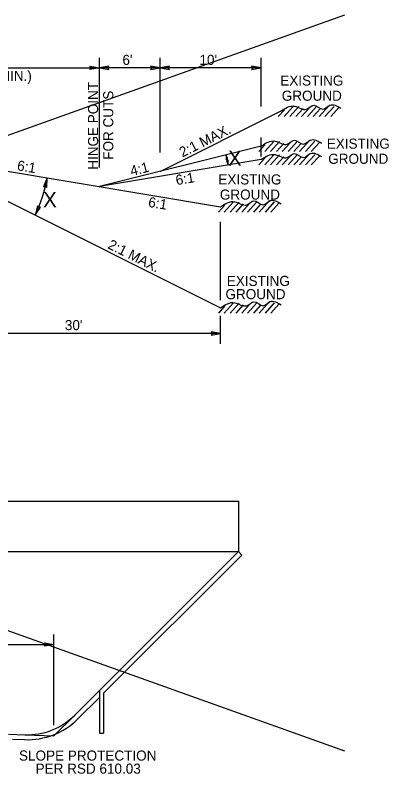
# Model space of a CAD drawing. Extents: x 1553195 to 1553792, y 810516 to 810787.
# Drawn here: x 1553619.9 to 1553656.8, y 810531.5 to 810606.6 of the extents above; entities that cross this region are included whole.
import ezdxf

# ---------------------------------------------------------------- set-up
doc = ezdxf.new("R2010")
doc.units = 0
for name, color, linetype in [('Prop DSN Text', 7, 'Continuous'), ('Prop Pavement Schedule Description CELL', 7, 'Continuous'), ('Sheet Sticker Incomplete CELL', 7, 'Continuous'), ('Typical Arrow Superelevation CELL', 7, 'Continuous'), ('Typical Text General CELL', 7, 'Continuous'), ('z - Construction', 7, 'Continuous')]:
    doc.layers.add(name, color=color, linetype=linetype)

msp = doc.modelspace()

# ---------------------------------------------------------------- linework, layer by layer
at = {"layer": 'Prop DSN Text'}
for points in [[(1553627.268, 810601.535), (1553628.206, 810601.374), (1553627.263, 810601.207), (1553627.383, 810601.374)], [(1553629.143, 810601.535), (1553628.206, 810601.374), (1553629.148, 810601.207), (1553629.028, 810601.374)], [(1553633.268, 810601.212), (1553634.206, 810601.374), (1553633.263, 810601.54), (1553633.383, 810601.374)], [(1553635.143, 810601.535), (1553634.206, 810601.374), (1553635.148, 810601.207), (1553635.028, 810601.374)], [(1553643.268, 810601.212), (1553644.206, 810601.374), (1553643.263, 810601.54), (1553643.383, 810601.374)], [(1553640.923, 810592.322), (1553640.736, 810592.76), (1553640.764, 810592.282), (1553640.831, 810592.36)], [(1553640.782, 810592.197), (1553640.946, 810591.751), (1553640.943, 810592.229), (1553640.872, 810592.155)], [(1553623.017, 810589.537), (1553623.043, 810590.488), (1553622.694, 810589.596), (1553622.881, 810589.681)], [(1553622.092, 810587.726), (1553621.846, 810586.807), (1553622.392, 810587.593), (1553622.191, 810587.554)], [(1553639.268, 810574.9), (1553640.206, 810575.062), (1553639.263, 810575.228), (1553639.383, 810575.062)], [(1553622.768, 810544.426), (1553623.706, 810544.264), (1553622.763, 810544.098), (1553622.883, 810544.264)]]:
    msp.add_lwpolyline(points, close=True, dxfattribs=at)
at = {"layer": 'Prop Pavement Schedule Description CELL'}
for p, q in [((1553628.206, 810591.507), (1553628.206, 810602.374)), ((1553640.206, 810578.372), (1553640.206, 810586.148)), ((1553640.206, 810574.062), (1553640.206, 810576.817)), ((1553623.706, 810536.295), (1553623.706, 810545.264))]:
    msp.add_line(p, q, dxfattribs=at)
for centre, radius, start, end in [((1553628.206, 810589.627), 12.916, 9.46232, 14.03624), ((1553610.206, 810592.627), 13.014, 333.43495, 350.53768)]:
    msp.add_arc(centre, radius, start, end, dxfattribs=at)
at = {"layer": 'Sheet Sticker Incomplete CELL'}
for p, q in [((1553634.206, 810591.127), (1553646.125, 810597.087)), ((1553644.206, 810593.627), (1553628.206, 810589.627)), ((1553610.206, 810592.627), (1553640.206, 810587.627)), ((1553610.206, 810592.627), (1553640.206, 810577.627)), ((1553644.206, 810592.294), (1553628.206, 810589.627))]:
    msp.add_line(p, q, dxfattribs=at)
at = {"layer": 'Typical Arrow Superelevation CELL'}
for p, q in [((1553652.472, 810606.601), (1553448.543, 810533.73)), ((1553448.543, 810606.601), (1553652.472, 810533.73)), ((1553446.448, 810558.478), (1553641.963, 810558.478)), ((1553641.963, 810558.478), (1553641.963, 810553.478)), ((1553446.448, 810553.478), (1553641.963, 810553.478)), ((1553625.739, 810537.254), (1553641.963, 810553.478)), ((1553641.963, 810553.478), (1553642.309, 810553.133)), ((1553628.628, 810539.452), (1553642.309, 810553.133)), ((1553628.206, 810539.687), (1553628.206, 810535.478)), ((1553626.084, 810536.908), (1553628.206, 810539.03)), ((1553628.628, 810539.452), (1553628.628, 810535.478)), ((1553623.706, 810535.22), (1553625.739, 810537.254)), ((1553619.206, 810535.398), (1553620.832, 810535.334)), ((1553620.832, 810535.334), (1553623.706, 810535.22)), ((1553628.206, 810535.478), (1553628.628, 810535.478)), ((1553619.628, 810534.893), (1553620.813, 810534.846))]:
    msp.add_line(p, q, dxfattribs=at)
for radius in [7.06, 6.572]:
    msp.add_arc((1553621.092, 810541.901), radius, 267.73793, 315, dxfattribs=at)
at = {"layer": 'Typical Text General CELL'}
for p, q in [((1553647.361, 810597.529), (1553646.486, 810596.556)), ((1553647.956, 810597.55), (1553647.062, 810596.556)), ((1553649.715, 810597.585), (1553648.79, 810596.556)), ((1553650.964, 810597.692), (1553649.942, 810596.556)), ((1553651.429, 810597.569), (1553650.518, 810596.556)), ((1553646.512, 810597.225), (1553645.91, 810596.556)), ((1553648.366, 810597.366), (1553647.638, 810596.556)), ((1553648.99, 810597.419), (1553648.214, 810596.556)), ((1553650.076, 810597.345), (1553649.366, 810596.556)), ((1553651.891, 810597.443), (1553651.094, 810596.556)), ((1553644.593, 810593.765), (1553643.991, 810593.097)), ((1553645.442, 810594.069), (1553644.567, 810593.097)), ((1553646.037, 810594.091), (1553645.143, 810593.097)), ((1553646.447, 810593.906), (1553645.719, 810593.097)), ((1553647.071, 810593.959), (1553646.295, 810593.097)), ((1553647.796, 810594.125), (1553646.871, 810593.097)), ((1553648.157, 810593.886), (1553647.447, 810593.097)), ((1553649.045, 810594.232), (1553648.023, 810593.097)), ((1553649.51, 810594.11), (1553648.599, 810593.097)), ((1553649.972, 810593.983), (1553649.175, 810593.097)), ((1553644.593, 810592.432), (1553643.991, 810591.764)), ((1553645.442, 810592.736), (1553644.567, 810591.764)), ((1553646.037, 810592.757), (1553645.143, 810591.764)), ((1553646.447, 810592.573), (1553645.719, 810591.764)), ((1553647.071, 810592.626), (1553646.295, 810591.764)), ((1553647.796, 810592.792), (1553646.871, 810591.764)), ((1553648.157, 810592.553), (1553647.447, 810591.764)), ((1553649.045, 810592.899), (1553648.023, 810591.764)), ((1553649.51, 810592.776), (1553648.599, 810591.764)), ((1553649.972, 810592.65), (1553649.175, 810591.764)), ((1553640.593, 810587.765), (1553639.991, 810587.097)), ((1553641.442, 810588.069), (1553640.567, 810587.097)), ((1553642.037, 810588.091), (1553641.143, 810587.097)), ((1553642.447, 810587.906), (1553641.719, 810587.097)), ((1553643.071, 810587.959), (1553642.295, 810587.097)), ((1553643.796, 810588.125), (1553642.871, 810587.097)), ((1553644.157, 810587.886), (1553643.447, 810587.097)), ((1553645.045, 810588.232), (1553644.023, 810587.097)), ((1553645.51, 810588.11), (1553644.599, 810587.097)), ((1553645.972, 810587.983), (1553645.175, 810587.097)), ((1553641.442, 810578.069), (1553640.567, 810577.097)), ((1553642.037, 810578.091), (1553641.143, 810577.097)), ((1553643.071, 810577.959), (1553642.295, 810577.097)), ((1553643.796, 810578.125), (1553642.871, 810577.097)), ((1553645.045, 810578.232), (1553644.023, 810577.097)), ((1553645.51, 810578.11), (1553644.599, 810577.097)), ((1553645.972, 810577.983), (1553645.175, 810577.097)), ((1553640.593, 810577.765), (1553639.991, 810577.097)), ((1553642.447, 810577.906), (1553641.719, 810577.097)), ((1553644.157, 810577.886), (1553643.447, 810577.097))]:
    msp.add_line(p, q, dxfattribs=at)
for points in [[(1553646.125, 810597.087), (1553647.519, 810597.585), (1553648.714, 810597.286), (1553649.411, 810597.685), (1553650.307, 810597.286), (1553651.004, 810597.685), (1553652.1, 810597.386)], [(1553644.206, 810593.627), (1553645.6, 810594.126), (1553646.795, 810593.827), (1553647.492, 810594.225), (1553648.388, 810593.827), (1553649.086, 810594.225), (1553650.181, 810593.926)], [(1553644.206, 810592.294), (1553645.6, 810592.792), (1553646.795, 810592.493), (1553647.492, 810592.892), (1553648.388, 810592.493), (1553649.086, 810592.892), (1553650.181, 810592.593)], [(1553640.206, 810587.627), (1553641.6, 810588.126), (1553642.795, 810587.827), (1553643.492, 810588.225), (1553644.388, 810587.827), (1553645.086, 810588.225), (1553646.181, 810587.926)], [(1553640.206, 810577.627), (1553641.6, 810578.126), (1553642.795, 810577.827), (1553643.492, 810578.225), (1553644.388, 810577.827), (1553645.086, 810578.225), (1553646.181, 810577.926)]]:
    msp.add_spline(points, degree=3, dxfattribs=at)
at = {"layer": 'z - Construction'}
for p, q in [((1553634.206, 810592.994), (1553634.206, 810602.374)), ((1553644.206, 810597.541), (1553644.206, 810602.374)), ((1553610.206, 810601.374), (1553628.206, 810601.374)), ((1553634.206, 810601.374), (1553628.206, 810601.374)), ((1553644.206, 810601.374), (1553634.206, 810601.374)), ((1553644.206, 810592.603), (1553644.206, 810594.493)), ((1553640.206, 810575.062), (1553610.206, 810575.062)), ((1553610.206, 810544.264), (1553623.706, 810544.264))]:
    msp.add_line(p, q, dxfattribs=at)

# ---------------------------------------------------------------- texts
at = {"layer": 'Prop Pavement Schedule Description CELL'}
for s, height, p in [("6'", 1, (1553630.491, 810601.674)), ("10'", 1, (1553638.11, 810601.674)), ("(15' MIN.)", 1, (1553615.698, 810600.086)), ('EXISTING', 1, (1553646.106, 810599.625)), ('GROUND', 1, (1553646.255, 810598.125)), ('EXISTING', 1, (1553650.702, 810593.378)), ('X', 1.5, (1553640.945, 810591.684)), ('GROUND', 1, (1553650.851, 810591.878)), ('EXISTING', 1, (1553639.979, 810589.833)), ('GROUND', 1, (1553640.129, 810588.333)), ('X', 1.5, (1553622.642, 810587.58)), ('EXISTING', 1, (1553640.812, 810579.782)), ('GROUND', 1, (1553640.682, 810578.471)), ("30'", 1, (1553624.794, 810575.406)), ('SLOPE PROTECTION', 1, (1553620.255, 810532.77)), ('PER RSD 610.03', 1, (1553621.898, 810531.475))]:
    msp.add_text(s, height=height, dxfattribs=at).set_placement(p)
for s, rotation, p in [('HINGE POINT', 90, (1553628.085, 810591.292)), ('FOR CUTS', 90, (1553629.585, 810592.285)), ('2:1 MAX.', 26.56505, (1553636.418, 810592.498)), ('6:1', 350.53768, (1553620.014, 810591.249)), ('4:1', 14.03624, (1553631.392, 810590.664)), ('6:1', 9.46232, (1553635.845, 810589.756)), ('6:1', 350.53768, (1553632.987, 810587.627)), ('2:1 MAX.', 333.43495, (1553628.953, 810583.548))]:
    msp.add_text(s, height=1, rotation=rotation, dxfattribs=at).set_placement(p)

doc.saveas('drawing.dxf')
